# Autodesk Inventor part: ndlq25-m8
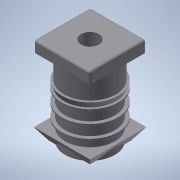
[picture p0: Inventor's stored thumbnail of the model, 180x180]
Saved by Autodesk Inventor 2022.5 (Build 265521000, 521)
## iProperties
Created: 2016-12
Part Number: ndlq25-m8
Material: 一般
Document SubType Name: Modeling
Designer: imaocorp
Density: 1 g/cm^3
Appearance: 既定
Author: imaocorp
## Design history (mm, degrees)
node "ndlq25-m8.x_t1"
node "ndlq25-m8"
node "Base1"
